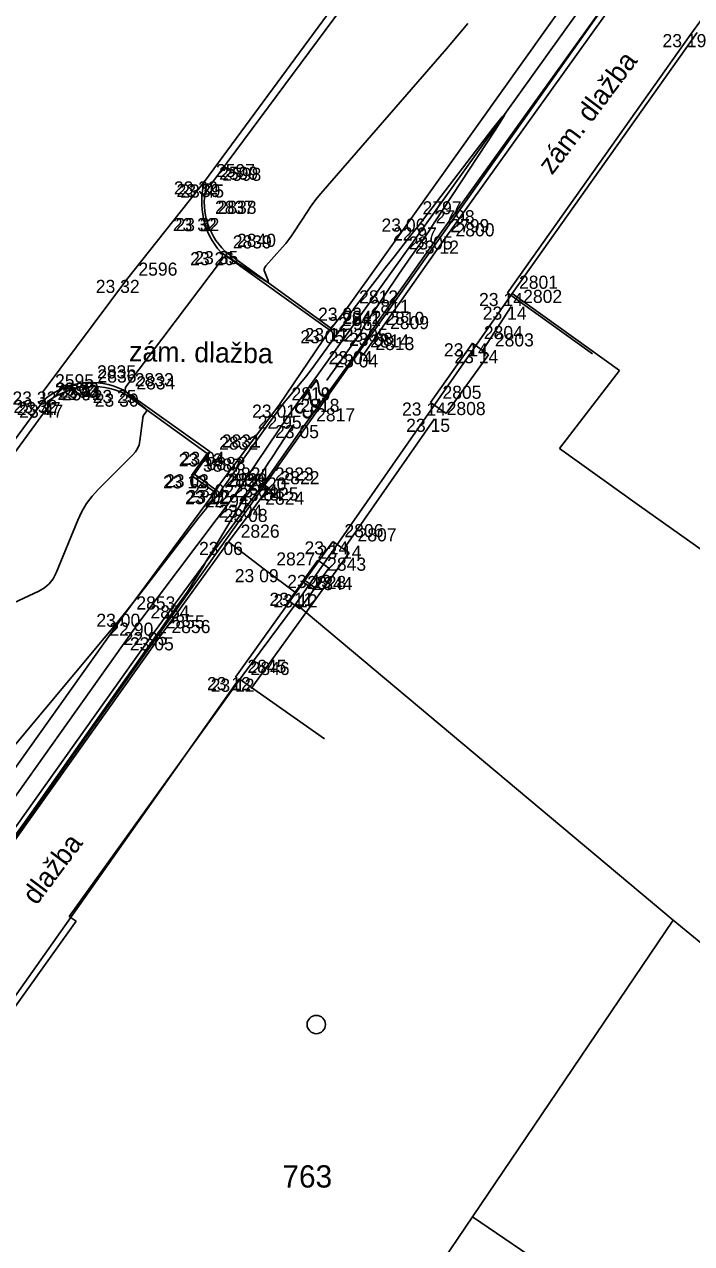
# Model space of a CAD drawing. Extents: x -702257 to -701487, y -1009871 to -1008841.
# Drawn here: x -701872.19 to -701859.46, y -1009561.05 to -1009537.78 of the extents above; entities that cross this region are included whole.
import ezdxf

# ---------------------------------------------------------------- set-up
doc = ezdxf.new("R2010")
doc.units = 0
for name, color, linetype in [('Ex_Contour Labels', 7, 'Continuous'), ('Ex_Major Contours', 7, 'Continuous'), ('Ex_Minor Contours', 7, 'Continuous'), ('Z_body', 7, 'Continuous'), ('Z_body_cisla', 7, 'Continuous'), ('Z_body_vysky_redukovane', 7, 'Continuous'), ('Z_budova', 7, 'Continuous'), ('Z_katastr_cisla_stavebni', 7, 'Continuous'), ('Z_katastr_hranice', 7, 'Continuous'), ('Z_katastr_vnitrni_kresba', 7, 'Continuous'), ('Z_katastr_znacky_budov', 7, 'Continuous'), ('Z_komunikace', 7, 'Continuous'), ('Z_obruba', 7, 'Continuous'), ('Z_pilire', 7, 'Continuous'), ('Z_ploty', 7, 'Continuous'), ('Z_popisy', 7, 'Continuous'), ('Z_rozhranni', 7, 'Continuous'), ('Z_vstupy', 7, 'Continuous'), ('Z_zlabek', 7, 'Continuous')]:
    doc.layers.add(name, color=color, linetype=linetype)

# ---------------------------------------------------------------- blocks, each defined once
blk = doc.blocks.new('POINT_DISPLAY')
blk.add_line((0, 0), (0, 0))
blk = doc.blocks.new('Z666')
for p, q in [((-0.25, 0.13), (-0.25, -0.13)), ((0.25, 0.13), (-0.25, 0.13)), ((0.25, -0.13), (0.25, 0.13)), ((-0.25, -0.13), (0.25, -0.13))]:
    blk.add_line(p, q)

msp = doc.modelspace()

# ---------------------------------------------------------------- linework, layer by layer
at = {"layer": 'Ex_Major Contours'}
for points in [[(-701866.421, -1009544.577), (-701866.412, -1009544.566), (-701866.341, -1009544.468), (-701866.27, -1009544.37), (-701865.853, -1009543.79), (-701865.833, -1009543.76), (-701865.813, -1009543.73), (-701865.793, -1009543.699), (-701865.775, -1009543.668), (-701865.702, -1009543.543), (-701865.683, -1009543.512), (-701865.664, -1009543.481), (-701865.645, -1009543.45), (-701865.625, -1009543.42), (-701865.042, -1009542.551), (-701864.986, -1009542.468), (-701864.929, -1009542.384), (-701864.872, -1009542.301), (-701864.814, -1009542.219), (-701864.581, -1009541.889), (-701864.523, -1009541.806), (-701864.466, -1009541.723), (-701864.41, -1009541.639), (-701864.354, -1009541.555), (-701863.205, -1009539.805), (-701863.05, -1009539.563), (-701863.006, -1009539.477), (-701863.073, -1009539.547), (-701863.25, -1009539.773), (-701864.491, -1009541.396), (-701864.571, -1009541.499), (-701864.651, -1009541.603), (-701864.731, -1009541.706), (-701864.811, -1009541.809), (-701865.134, -1009542.22), (-701865.214, -1009542.322), (-701865.295, -1009542.425), (-701865.375, -1009542.528), (-701865.455, -1009542.632), (-701865.895, -1009543.203), (-701865.916, -1009543.23), (-701865.936, -1009543.259), (-701865.955, -1009543.287), (-701865.973, -1009543.317), (-701866.044, -1009543.436), (-701866.062, -1009543.465), (-701866.081, -1009543.494), (-701866.1, -1009543.523), (-701866.12, -1009543.551), (-701866.633, -1009544.265), (-701866.695, -1009544.35), (-701866.758, -1009544.433), (-701866.823, -1009544.514), (-701866.889, -1009544.595), (-701867.158, -1009544.915), (-701867.224, -1009544.996), (-701867.288, -1009545.077), (-701867.352, -1009545.161), (-701867.413, -1009545.245), (-701868.011, -1009546.081), (-701868.048, -1009546.133), (-701868.086, -1009546.186), (-701868.123, -1009546.238), (-701868.161, -1009546.291), (-701868.371, -1009546.588), (-701868.378, -1009546.598), (-701868.385, -1009546.608), (-701868.391, -1009546.618), (-701868.398, -1009546.628), (-701868.424, -1009546.669), (-701868.431, -1009546.68), (-701868.438, -1009546.69), (-701868.446, -1009546.699), (-701868.453, -1009546.709), (-701868.691, -1009546.991), (-701868.733, -1009547.042), (-701868.774, -1009547.093), (-701868.815, -1009547.144), (-701868.855, -1009547.196), (-701869.896, -1009548.545), (-701870.084, -1009548.787), (-701870.275, -1009549.026), (-701870.468, -1009549.264), (-701870.663, -1009549.499), (-701875.719, -1009555.543)], [(-701872.359, -1009553.263), (-701872.088, -1009552.88), (-701871.818, -1009552.497), (-701871.548, -1009552.114), (-701871.278, -1009551.731), (-701869.807, -1009549.639), (-701869.733, -1009549.535), (-701869.66, -1009549.43), (-701869.585, -1009549.326), (-701869.511, -1009549.222), (-701869.162, -1009548.734), (-701869.114, -1009548.666), (-701869.067, -1009548.597), (-701869.022, -1009548.527), (-701868.977, -1009548.456), (-701868.803, -1009548.172), (-701868.759, -1009548.101), (-701868.716, -1009548.03), (-701868.673, -1009547.959), (-701868.629, -1009547.887), (-701868.054, -1009546.932), (-701868.034, -1009546.901), (-701868.015, -1009546.871), (-701867.994, -1009546.841), (-701867.973, -1009546.812), (-701867.886, -1009546.695), (-701867.864, -1009546.665), (-701867.843, -1009546.635), (-701867.822, -1009546.605), (-701867.802, -1009546.575), (-701867.52, -1009546.138), (-701867.468, -1009546.058), (-701867.416, -1009545.978), (-701867.364, -1009545.898), (-701867.311, -1009545.818), (-701867.1, -1009545.499), (-701867.047, -1009545.42), (-701867.047, -1009545.42)]]:
    msp.add_lwpolyline(points, dxfattribs=at)
at = {"layer": 'Ex_Minor Contours'}
msp.add_lwpolyline([(-701863.726, -1009537.766), (-701863.928, -1009538.011), (-701864.134, -1009538.253), (-701866.53, -1009541.011), (-701866.599, -1009541.093), (-701866.665, -1009541.178), (-701866.728, -1009541.265), (-701866.787, -1009541.354), (-701867.036, -1009541.741), (-701867.087, -1009541.817), (-701867.142, -1009541.892), (-701867.199, -1009541.964), (-701867.259, -1009542.034), (-701867.579, -1009542.392), (-701867.599, -1009542.421), (-701867.61, -1009542.451), (-701867.61, -1009542.483), (-701867.601, -1009542.516), (-701867.538, -1009542.675), (-701867.532, -1009542.694), (-701867.534, -1009542.704), (-701867.544, -1009542.704), (-701867.562, -1009542.695), (-701867.65, -1009542.641), (-701867.671, -1009542.627), (-701867.693, -1009542.613), (-701867.715, -1009542.599), (-701867.737, -1009542.586), (-701868.326, -1009542.21), (-701868.333, -1009542.207), (-701868.341, -1009542.206), (-701868.348, -1009542.208), (-701868.355, -1009542.212), (-701868.382, -1009542.235), (-701868.388, -1009542.241), (-701868.394, -1009542.247), (-701868.4, -1009542.254), (-701868.406, -1009542.261), (-701870.234, -1009544.673), (-701870.257, -1009544.715), (-701870.262, -1009544.756), (-701870.249, -1009544.794), (-701870.216, -1009544.831), (-701869.995, -1009545.017), (-701869.965, -1009545.043), (-701869.934, -1009545.069), (-701869.869, -1009545.124), (-701869.858, -1009545.136), (-701869.853, -1009545.148), (-701869.855, -1009545.162), (-701869.862, -1009545.176), (-701869.904, -1009545.234), (-701869.913, -1009545.249), (-701869.92, -1009545.265), (-701869.926, -1009545.282), (-701869.929, -1009545.299), (-701869.983, -1009545.732), (-701869.999, -1009545.808), (-701870.026, -1009545.877), (-701870.065, -1009545.941), (-701870.115, -1009545.999), (-701870.774, -1009546.653), (-701870.895, -1009546.785), (-701871.001, -1009546.928), (-701871.092, -1009547.08), (-701871.167, -1009547.243), (-701871.578, -1009548.249), (-701871.636, -1009548.362), (-701871.711, -1009548.458), (-701871.803, -1009548.538), (-701871.913, -1009548.602), (-701872.384, -1009548.824)], dxfattribs=at)
at = {"layer": 'Z_budova'}
for p, q in [((-701859.47, -1009537.97), (-701855.92, -1009533.05)), ((-701859.47, -1009537.97), (-701862.97, -1009542.91)), ((-701862.97, -1009542.91), (-701861.35, -1009544.07)), ((-701868.09, -1009550.27), (-701874.35, -1009559.14)), ((-701868.09, -1009550.27), (-701866.46, -1009551.42))]:
    msp.add_line(p, q, dxfattribs=at)
at = {"layer": 'Z_katastr_hranice'}
for p, q in [((-701769.49, -1009408.19), (-701878.35, -1009561.73)), ((-701859.35, -1009537.94), (-701862.88, -1009542.92)), ((-701862.88, -1009542.92), (-701867.01, -1009548.84)), ((-701867.01, -1009548.84), (-701868.02, -1009550.2)), ((-701867.01, -1009548.84), (-701859.81, -1009554.88)), ((-701868.02, -1009550.2), (-701871.33, -1009554.81)), ((-701871.33, -1009554.81), (-701871.2, -1009554.9)), ((-701859.81, -1009554.88), (-701856.15, -1009557.87)), ((-701871.2, -1009554.9), (-701874.22, -1009559.11))]:
    msp.add_line(p, q, dxfattribs=at)
at = {"layer": 'Z_katastr_vnitrni_kresba'}
for p, q in [((-701862.88, -1009542.92), (-701860.83, -1009544.39)), ((-701860.83, -1009544.39), (-701861.98, -1009545.88)), ((-701861.98, -1009545.88), (-701860.45, -1009546.97)), ((-701860.45, -1009546.97), (-701856.32, -1009549.91)), ((-701859.81, -1009554.88), (-701863.64, -1009560.54)), ((-701863.64, -1009560.54), (-701865.89, -1009563.87)), ((-701863.64, -1009560.54), (-701860.5, -1009562.66))]:
    msp.add_line(p, q, dxfattribs=at)
at = {"layer": 'Z_katastr_znacky_budov'}
msp.add_circle((-701866.617, -1009556.869), 0.175, dxfattribs=at)
at = {"layer": 'Z_komunikace'}
for p, q in [((-701868.75, -1009540.78), (-701862.96, -1009532.92)), ((-701870.24, -1009542.66), (-701868.75, -1009540.78)), ((-701870.24, -1009542.66), (-701871.83, -1009544.79)), ((-701871.83, -1009544.79), (-701871.81, -1009544.95)), ((-701874.59, -1009548.73), (-701871.81, -1009544.95))]:
    msp.add_line(p, q, dxfattribs=at)
at = {"layer": 'Z_obruba'}
for p, q in [((-701862.84, -1009533.03), (-701868.63, -1009540.84)), ((-701860.73, -1009536.86), (-701864.29, -1009541.83)), ((-701864.19, -1009541.91), (-701860.65, -1009536.97)), ((-701868.7, -1009540.83), (-701868.63, -1009540.84)), ((-701865.53, -1009543.59), (-701864.29, -1009541.83)), ((-701864.19, -1009541.91), (-701865.43, -1009543.67)), ((-701868.44, -1009542.13), (-701866.36, -1009543.62)), ((-701866.34, -1009543.58), (-701868.36, -1009542.11)), ((-701866.36, -1009543.62), (-701866.34, -1009543.58)), ((-701865.82, -1009544.02), (-701865.53, -1009543.59)), ((-701865.43, -1009543.67), (-701865.71, -1009544.08)), ((-701865.71, -1009544.08), (-701865.82, -1009544.02)), ((-701870.3, -1009544.76), (-701868.64, -1009545.94)), ((-701868.7, -1009545.97), (-701870.28, -1009544.83)), ((-701871.7, -1009545.04), (-701874.5, -1009548.86)), ((-701871.7, -1009545.04), (-701871.75, -1009544.99)), ((-701868.7, -1009545.97), (-701869, -1009546.39)), ((-701868.64, -1009545.94), (-701868.94, -1009546.37)), ((-701868.58, -1009546.69), (-701869, -1009546.39)), ((-701868.53, -1009546.67), (-701868.94, -1009546.37)), ((-701868.53, -1009546.67), (-701868.58, -1009546.69)), ((-701867.92, -1009546.95), (-701867.63, -1009546.56)), ((-701867.53, -1009546.63), (-701867.82, -1009547.03)), ((-701867.63, -1009546.56), (-701867.53, -1009546.63)), ((-701867.92, -1009546.95), (-701869.71, -1009549.38)), ((-701868.29, -1009547.66), (-701867.82, -1009547.03)), ((-701869.61, -1009549.48), (-701868.29, -1009547.66)), ((-701869.71, -1009549.38), (-701875.79, -1009557.93)), ((-701875.68, -1009557.99), (-701869.61, -1009549.48))]:
    msp.add_line(p, q, dxfattribs=at)
for centre, major_axis, ratio, start_param, end_param in [((-701867.39, -1009541.169), (-0.041, -1.434), 0.985495, 4.465745, 5.474754), ((-701867.562, -1009541.221), (0.444, -1.147), 0.963828, 4.030048, 5.167706), ((-701870.925, -1009545.959), (-1.255, -0.524), 0.985509, 3.843595, 5.032579), ((-701870.903, -1009546.106), (0.978, 1.032), 0.984595, 0.308149, 1.409821)]:
    msp.add_ellipse(centre, major_axis=major_axis, ratio=ratio, start_param=start_param, end_param=end_param, dxfattribs=at)
at = {"layer": 'Z_ploty'}
for p, q in [((-701864.44, -1009545), (-701863.64, -1009543.87)), ((-701863.33, -1009544.09), (-701863.64, -1009543.87)), ((-701864.14, -1009545.21), (-701863.33, -1009544.09)), ((-701864.44, -1009545), (-701864.14, -1009545.21)), ((-701867.01, -1009548.63), (-701866.3, -1009547.65)), ((-701865.99, -1009547.87), (-701866.3, -1009547.65)), ((-701867.86, -1009550.46), (-701865.99, -1009547.87)), ((-701868.16, -1009550.24), (-701867.01, -1009548.63))]:
    msp.add_line(p, q, dxfattribs=at)
at = {"layer": 'Z_rozhranni'}
for p, q in [((-701868.29, -1009547.66), (-701867.61, -1009548.18)), ((-701867.61, -1009548.18), (-701867.01, -1009548.63))]:
    msp.add_line(p, q, dxfattribs=at)
at = {"layer": 'Z_vstupy'}
for p, q in [((-701863.44, -1009544), (-701862.9, -1009543.17)), ((-701866.05, -1009547.73), (-701864.36, -1009545.31))]:
    msp.add_line(p, q, dxfattribs=at)
at = {"layer": 'Z_zlabek'}
for p, q in [((-701861.24, -1009536.48), (-701864.81, -1009541.49)), ((-701864.57, -1009541.66), (-701861, -1009536.67)), ((-701864.81, -1009541.49), (-701866.02, -1009543.19)), ((-701865.8, -1009543.37), (-701864.57, -1009541.66)), ((-701866.02, -1009543.19), (-701866.36, -1009543.62)), ((-701867.15, -1009545.25), (-701865.8, -1009543.37)), ((-701866.36, -1009543.62), (-701867.32, -1009545.04)), ((-701865.82, -1009544.02), (-701866.84, -1009545.43)), ((-701867.32, -1009545.04), (-701868.46, -1009546.56)), ((-701868.16, -1009546.75), (-701867.15, -1009545.25)), ((-701866.84, -1009545.43), (-701867.63, -1009546.56)), ((-701868.53, -1009546.67), (-701870.27, -1009549.03)), ((-701870, -1009549.2), (-701868.16, -1009546.75)), ((-701868.46, -1009546.56), (-701868.53, -1009546.67)), ((-701870.27, -1009549.03), (-701876.33, -1009557.55)), ((-701876.07, -1009557.73), (-701870, -1009549.2))]:
    msp.add_line(p, q, dxfattribs=at)

# ---------------------------------------------------------------- block references
at = {"layer": 'Z_body'}
for p in [(-701859.47, -1009537.97), (-701868.75, -1009540.78), (-701868.7, -1009540.83), (-701868.63, -1009540.84), (-701868.77, -1009541.48), (-701868.72, -1009541.48), (-701864.81, -1009541.49), (-701864.57, -1009541.66), (-701864.29, -1009541.83), (-701864.19, -1009541.91), (-701868.44, -1009542.13), (-701868.36, -1009542.11), (-701870.24, -1009542.66), (-701862.97, -1009542.91), (-701866.02, -1009543.19), (-701862.9, -1009543.17), (-701865.8, -1009543.37), (-701866.36, -1009543.62), (-701866.34, -1009543.58), (-701865.53, -1009543.59), (-701865.43, -1009543.67), (-701863.64, -1009543.87), (-701865.82, -1009544.02), (-701865.71, -1009544.08), (-701863.44, -1009544), (-701871.02, -1009544.62), (-701871.83, -1009544.79), (-701871.01, -1009544.7), (-701870.3, -1009544.76), (-701870.28, -1009544.83), (-701871.81, -1009544.95), (-701871.75, -1009544.99), (-701871.7, -1009545.04), (-701867.32, -1009545.04), (-701864.44, -1009545), (-701867.15, -1009545.25), (-701864.36, -1009545.31), (-701866.84, -1009545.43), (-701868.7, -1009545.97), (-701868.64, -1009545.94), (-701869, -1009546.39), (-701868.94, -1009546.37), (-701868.58, -1009546.69), (-701868.53, -1009546.67), (-701868.46, -1009546.56), (-701868.16, -1009546.75), (-701867.63, -1009546.56), (-701867.53, -1009546.63), (-701867.92, -1009546.95), (-701867.82, -1009547.03), (-701868.29, -1009547.66), (-701866.3, -1009547.65), (-701866.05, -1009547.73), (-701867.61, -1009548.18), (-701866.63, -1009548.29), (-701867.01, -1009548.63), (-701866.89, -1009548.66), (-701870.27, -1009549.03), (-701870, -1009549.2), (-701869.71, -1009549.38), (-701869.61, -1009549.48), (-701868.16, -1009550.24), (-701868.09, -1009550.27)]:
    msp.add_blockref('POINT_DISPLAY', p, dxfattribs=at)
at = {"layer": 'Z_pilire', "rotation": 54}
for p in [(-701866.63, -1009548.29), (-701866.89, -1009548.66)]:
    msp.add_blockref('Z666', p, dxfattribs=at)

# ---------------------------------------------------------------- texts
at = {"layer": 'Ex_Contour Labels'}
msp.add_text('223', height=0.35, rotation=233.3842, dxfattribs=at).set_placement((-701866.605, -1009544.531))
at = {"layer": 'Z_body_cisla'}
for s, p in [('2597', (-701868.53, -1009540.7)), ('2599', (-701868.47, -1009540.75)), ('2598', (-701868.41, -1009540.77)), ('2837', (-701868.55, -1009541.4)), ('2838', (-701868.5, -1009541.4)), ('2797', (-701864.59, -1009541.41)), ('2798', (-701864.34, -1009541.58)), ('2799', (-701864.06, -1009541.75)), ('2800', (-701863.96, -1009541.83)), ('2839', (-701868.21, -1009542.06)), ('2840', (-701868.13, -1009542.03)), ('2596', (-701870.01, -1009542.58)), ('2801', (-701862.75, -1009542.83)), ('2812', (-701865.8, -1009543.11)), ('2802', (-701862.67, -1009543.1)), ('2842', (-701866.12, -1009543.5)), ('2811', (-701865.58, -1009543.29)), ('2841', (-701866.13, -1009543.54)), ('2810', (-701865.3, -1009543.52)), ('2809', (-701865.21, -1009543.6)), ('2814', (-701865.59, -1009543.95)), ('2804', (-701863.42, -1009543.79)), ('2803', (-701863.21, -1009543.93)), ('2813', (-701865.49, -1009544)), ('2835', (-701870.8, -1009544.54)), ('2836', (-701870.79, -1009544.62)), ('2595', (-701871.6, -1009544.71)), ('2592', (-701871.59, -1009544.87)), ('2593', (-701871.53, -1009544.91)), ('2833', (-701870.08, -1009544.69)), ('2834', (-701870.05, -1009544.75)), ('2594', (-701871.47, -1009544.96)), ('2819', (-701867.09, -1009544.96)), ('2805', (-701864.21, -1009544.93)), ('2818', (-701866.92, -1009545.18)), ('2817', (-701866.62, -1009545.36)), ('2808', (-701864.13, -1009545.24)), ('2832', (-701868.47, -1009545.9)), ('2831', (-701868.42, -1009545.86)), ('3888', (-701868.71, -1009546.29)), ('3887', (-701868.78, -1009546.32)), ('2821', (-701868.24, -1009546.49)), ('2823', (-701867.41, -1009546.49)), ('2830', (-701868.35, -1009546.61)), ('2829', (-701868.3, -1009546.6)), ('2820', (-701867.93, -1009546.68)), ('2822', (-701867.3, -1009546.56)), ('2825', (-701867.7, -1009546.87)), ('2824', (-701867.59, -1009546.95)), ('2826', (-701868.06, -1009547.58)), ('2806', (-701866.08, -1009547.57)), ('2807', (-701865.83, -1009547.65)), ('2827', (-701867.38, -1009548.11)), ('2843', (-701866.41, -1009548.21)), ('2828', (-701866.79, -1009548.56)), ('2844', (-701866.67, -1009548.58)), ('2853', (-701870.05, -1009548.95)), ('2854', (-701869.78, -1009549.12)), ('2855', (-701869.49, -1009549.31)), ('2856', (-701869.38, -1009549.4)), ('2845', (-701867.93, -1009550.16)), ('2846', (-701867.87, -1009550.2))]:
    msp.add_text(s, height=0.25, dxfattribs=at).set_placement(p)
at = {"layer": 'Z_body_vysky_redukovane'}
for s, p in [('23 19', (-701860.012, -1009538.22)), ('23 32', (-701869.333, -1009541.03)), ('23 39', (-701869.283, -1009541.08)), ('23 45', (-701869.213, -1009541.09)), ('23 32', (-701869.353, -1009541.73)), ('23 32', (-701869.303, -1009541.73)), ('23 06', (-701865.373, -1009541.74)), ('22 97', (-701865.153, -1009541.91)), ('23 05', (-701864.853, -1009542.08)), ('23 12', (-701864.732, -1009542.16)), ('23 26', (-701869.023, -1009542.38)), ('23 35', (-701868.943, -1009542.36)), ('23 32', (-701870.823, -1009542.91)), ('23 14', (-701863.512, -1009543.16)), ('23 03', (-701866.583, -1009543.44)), ('23 14', (-701863.442, -1009543.42)), ('22 95', (-701866.383, -1009543.62)), ('23 05', (-701866.922, -1009543.87)), ('23 11', (-701866.84, -1009543.83)), ('23 05', (-701866.093, -1009543.84)), ('23 08', (-701865.993, -1009543.92)), ('23 14', (-701864.182, -1009544.12)), ('23 04', (-701866.382, -1009544.27)), ('23 04', (-701866.273, -1009544.33)), ('23 14', (-701863.982, -1009544.25)), ('23 32', (-701871.603, -1009544.87)), ('23 32', (-701872.413, -1009545.04)), ('23 41', (-701871.552, -1009544.95)), ('23 25', (-701870.883, -1009545.01)), ('23 30', (-701870.843, -1009545.08)), ('23 32', (-701872.393, -1009545.2)), ('23 47', (-701872.333, -1009545.24)), ('23 47', (-701872.283, -1009545.29)), ('23 01', (-701867.841, -1009545.29)), ('23 14', (-701864.982, -1009545.25)), ('22 95', (-701867.733, -1009545.5)), ('23 15', (-701864.902, -1009545.56)), ('23 05', (-701867.403, -1009545.68)), ('23 12', (-701869.242, -1009546.22)), ('23 04', (-701869.203, -1009546.19)), ('23 12', (-701869.542, -1009546.64)), ('23 03', (-701869.502, -1009546.62)), ('23 12', (-701869.122, -1009546.94)), ('23 02', (-701869.093, -1009546.92)), ('23 02', (-701869.023, -1009546.81)), ('22 94', (-701868.743, -1009547)), ('23 04', (-701868.193, -1009546.81)), ('23 04', (-701868.093, -1009546.88)), ('23 04', (-701868.483, -1009547.2)), ('23 08', (-701868.382, -1009547.28)), ('23 06', (-701868.853, -1009547.91)), ('23 14', (-701866.842, -1009547.9)), ('23 14', (-701866.592, -1009547.98)), ('23 09', (-701868.172, -1009548.43)), ('23 13', (-701867.172, -1009548.54)), ('23 11', (-701867.51, -1009548.88)), ('23 12', (-701867.432, -1009548.91)), ('23 00', (-701870.812, -1009549.28)), ('22 90', (-701870.562, -1009549.45)), ('22 95', (-701870.293, -1009549.63)), ('23 05', (-701870.172, -1009549.73)), ('23 12', (-701868.702, -1009550.49)), ('23 12', (-701868.632, -1009550.52))]:
    msp.add_text(s, height=0.25, dxfattribs=at).set_placement(p)
at = {"layer": 'Z_katastr_cisla_stavebni'}
msp.add_text('763', height=0.425, dxfattribs=at).set_placement((-701867.263, -1009559.98))
at = {"layer": 'Z_popisy'}
for s, rotation, p in [('zám. dlažba', 53.1, (-701862.119, -1009540.673)), ('zám. dlažba', 359.1, (-701870.189, -1009544.211)), ('dlažba', 53.1, (-701871.955, -1009554.608))]:
    msp.add_text(s, height=0.38, rotation=rotation, dxfattribs=at).set_placement(p)

doc.saveas('drawing.dxf')
